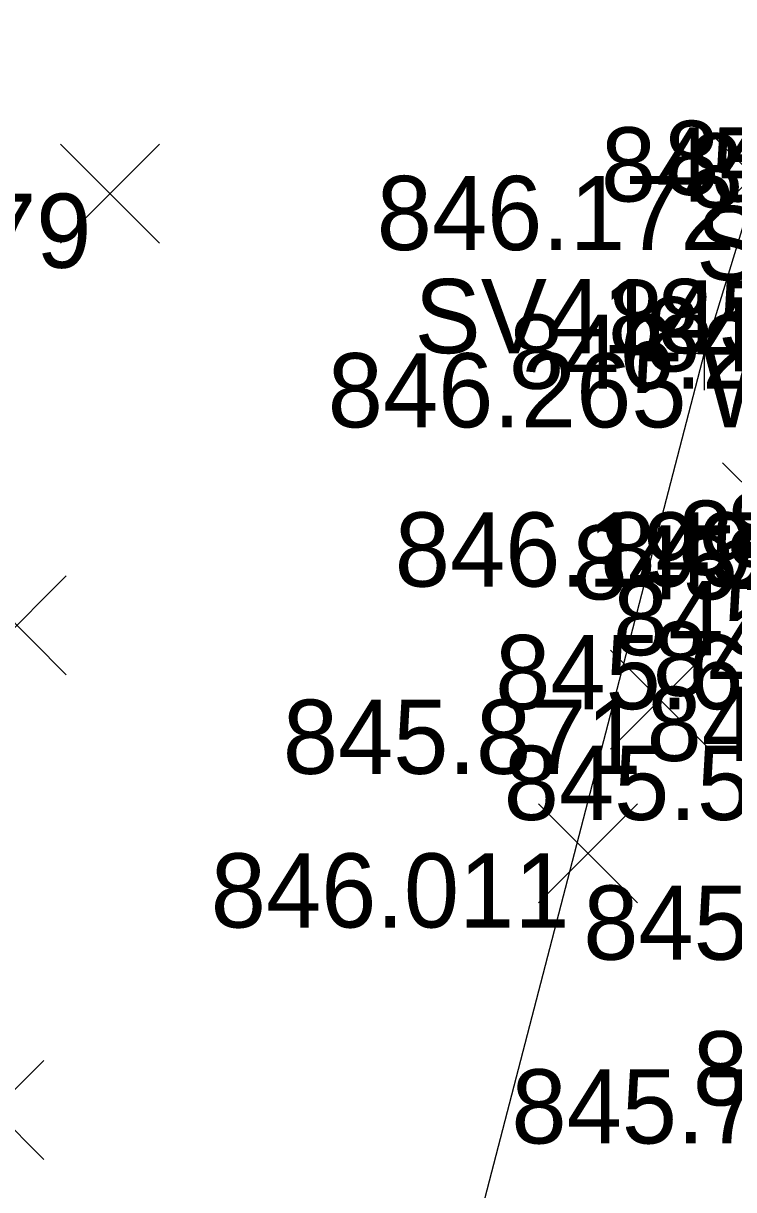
# Model space of a CAD drawing. Extents: x 2228183 to 2230895, y 679226 to 682223.
# Drawn here: x 2228365.44 to 2228375.01, y 680584.85 to 680600.58 of the extents above; entities that cross this region are included whole.
import ezdxf

# ---------------------------------------------------------------- set-up
doc = ezdxf.new("R2010")
doc.units = 0
for name, color, linetype in [('SC_Scratch1', 7, 'Continuous'), ('SV_P_Control_Cells_Set', 7, 'Continuous'), ('SV_X_Random_Point', 7, 'Continuous'), ('SV_X_Shot_Marker', 7, 'Continuous'), ('SV_X_Text_Comment', 7, 'Continuous'), ('VG_X_Tree_Line_Rt', 7, 'Continuous')]:
    doc.layers.add(name, color=color, linetype=linetype)

msp = doc.modelspace()

# ---------------------------------------------------------------- linework, layer by layer
at = {"layer": 'SV_X_Random_Point'}
for p, q in [((2228374.602, 680597.856), (2228375.936, 680599.191)), ((2228374.602, 680599.191), (2228375.936, 680597.856)), ((2228365.935, 680597.617), (2228367.269, 680598.952)), ((2228365.935, 680598.952), (2228367.269, 680597.617)), ((2228374.856, 680593.319), (2228376.19, 680594.654)), ((2228374.856, 680594.654), (2228376.19, 680593.319)), ((2228364.68, 680591.798), (2228366.014, 680593.133)), ((2228364.68, 680593.133), (2228366.014, 680591.798)), ((2228373.346, 680590.794), (2228374.68, 680592.129)), ((2228373.346, 680592.129), (2228374.68, 680590.794)), ((2228372.375, 680588.722), (2228373.709, 680590.057)), ((2228372.375, 680590.057), (2228373.709, 680588.722)), ((2228364.379, 680585.263), (2228365.713, 680586.598)), ((2228364.379, 680586.598), (2228365.713, 680585.263))]:
    msp.add_line(p, q, dxfattribs=at)
at = {"layer": 'SV_X_Shot_Marker'}
for p, q in [((2228374.606, 680596.633), (2228374.606, 680595.633)), ((2228374.106, 680596.133), (2228375.106, 680596.133)), ((2228374.606, 680596.133), (2228374.606, 680596.133))]:
    msp.add_line(p, q, dxfattribs=at)
at = {"layer": 'VG_X_Tree_Line_Rt'}
msp.add_lwpolyline([(2228410.452, 680773.345), (2228402.142, 680728.483), (2228403.602, 680691.208), (2228374.606, 680596.133), (2228370.969, 680582.119), (2228367.614, 680567.008), (2228346.3, 680486.661), (2228340.655, 680455.186), (2228334.048, 680383.235)], dxfattribs=at)

# ---------------------------------------------------------------- texts
at = {"layer": 'SC_Scratch1'}
for s, p in [('845.959', (2228374.068, 680598.266)), ('845.980', (2228373.217, 680598.178)), ('843.982', (2228374.39, 680598.095)), ('846.172', (2228370.196, 680597.523)), ('846.179', (2228361.518, 680597.284)), ('845.951', (2228373.314, 680596.117)), ('844.517', (2228373.814, 680595.888)), ('846.229', (2228371.978, 680595.653)), ('846.265', (2228369.536, 680595.133)), ('844.586', (2228374.913, 680593.252)), ('845.663', (2228374.26, 680593.144)), ('846.199', (2228370.439, 680592.986)), ('845.759', (2228373.209, 680592.986)), ('845.932', (2228372.833, 680592.813)), ('845.650', (2228373.381, 680592.061)), ('845.367', (2228373.916, 680591.513)), ('845.614', (2228371.792, 680591.333)), ('845.562', (2228373.832, 680590.635)), ('845.871', (2228368.931, 680590.461)), ('845.545', (2228371.907, 680589.839)), ('846.011', (2228367.96, 680588.389)), ('845.818', (2228372.979, 680587.955)), ('845.597', (2228374.456, 680585.99)), ('845.788', (2228372.011, 680585.477))]:
    msp.add_text(s, height=1, dxfattribs=at).set_placement(p)
at = {"layer": 'SV_P_Control_Cells_Set'}
for s, p in [('SV897', (2228374.5, 680597.117)), ('SV418', (2228370.706, 680596.133))]:
    msp.add_text(s, height=1, dxfattribs=at).set_placement(p)
at = {"layer": 'SV_X_Text_Comment'}
msp.add_text('WOODSR', height=1, dxfattribs=at).set_placement((2228374.606, 680595.133))

doc.saveas('drawing.dxf')
